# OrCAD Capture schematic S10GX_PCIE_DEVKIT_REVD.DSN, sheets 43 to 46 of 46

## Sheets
43 Power - 5V, 2.5V, 2.4V, 1V: size C
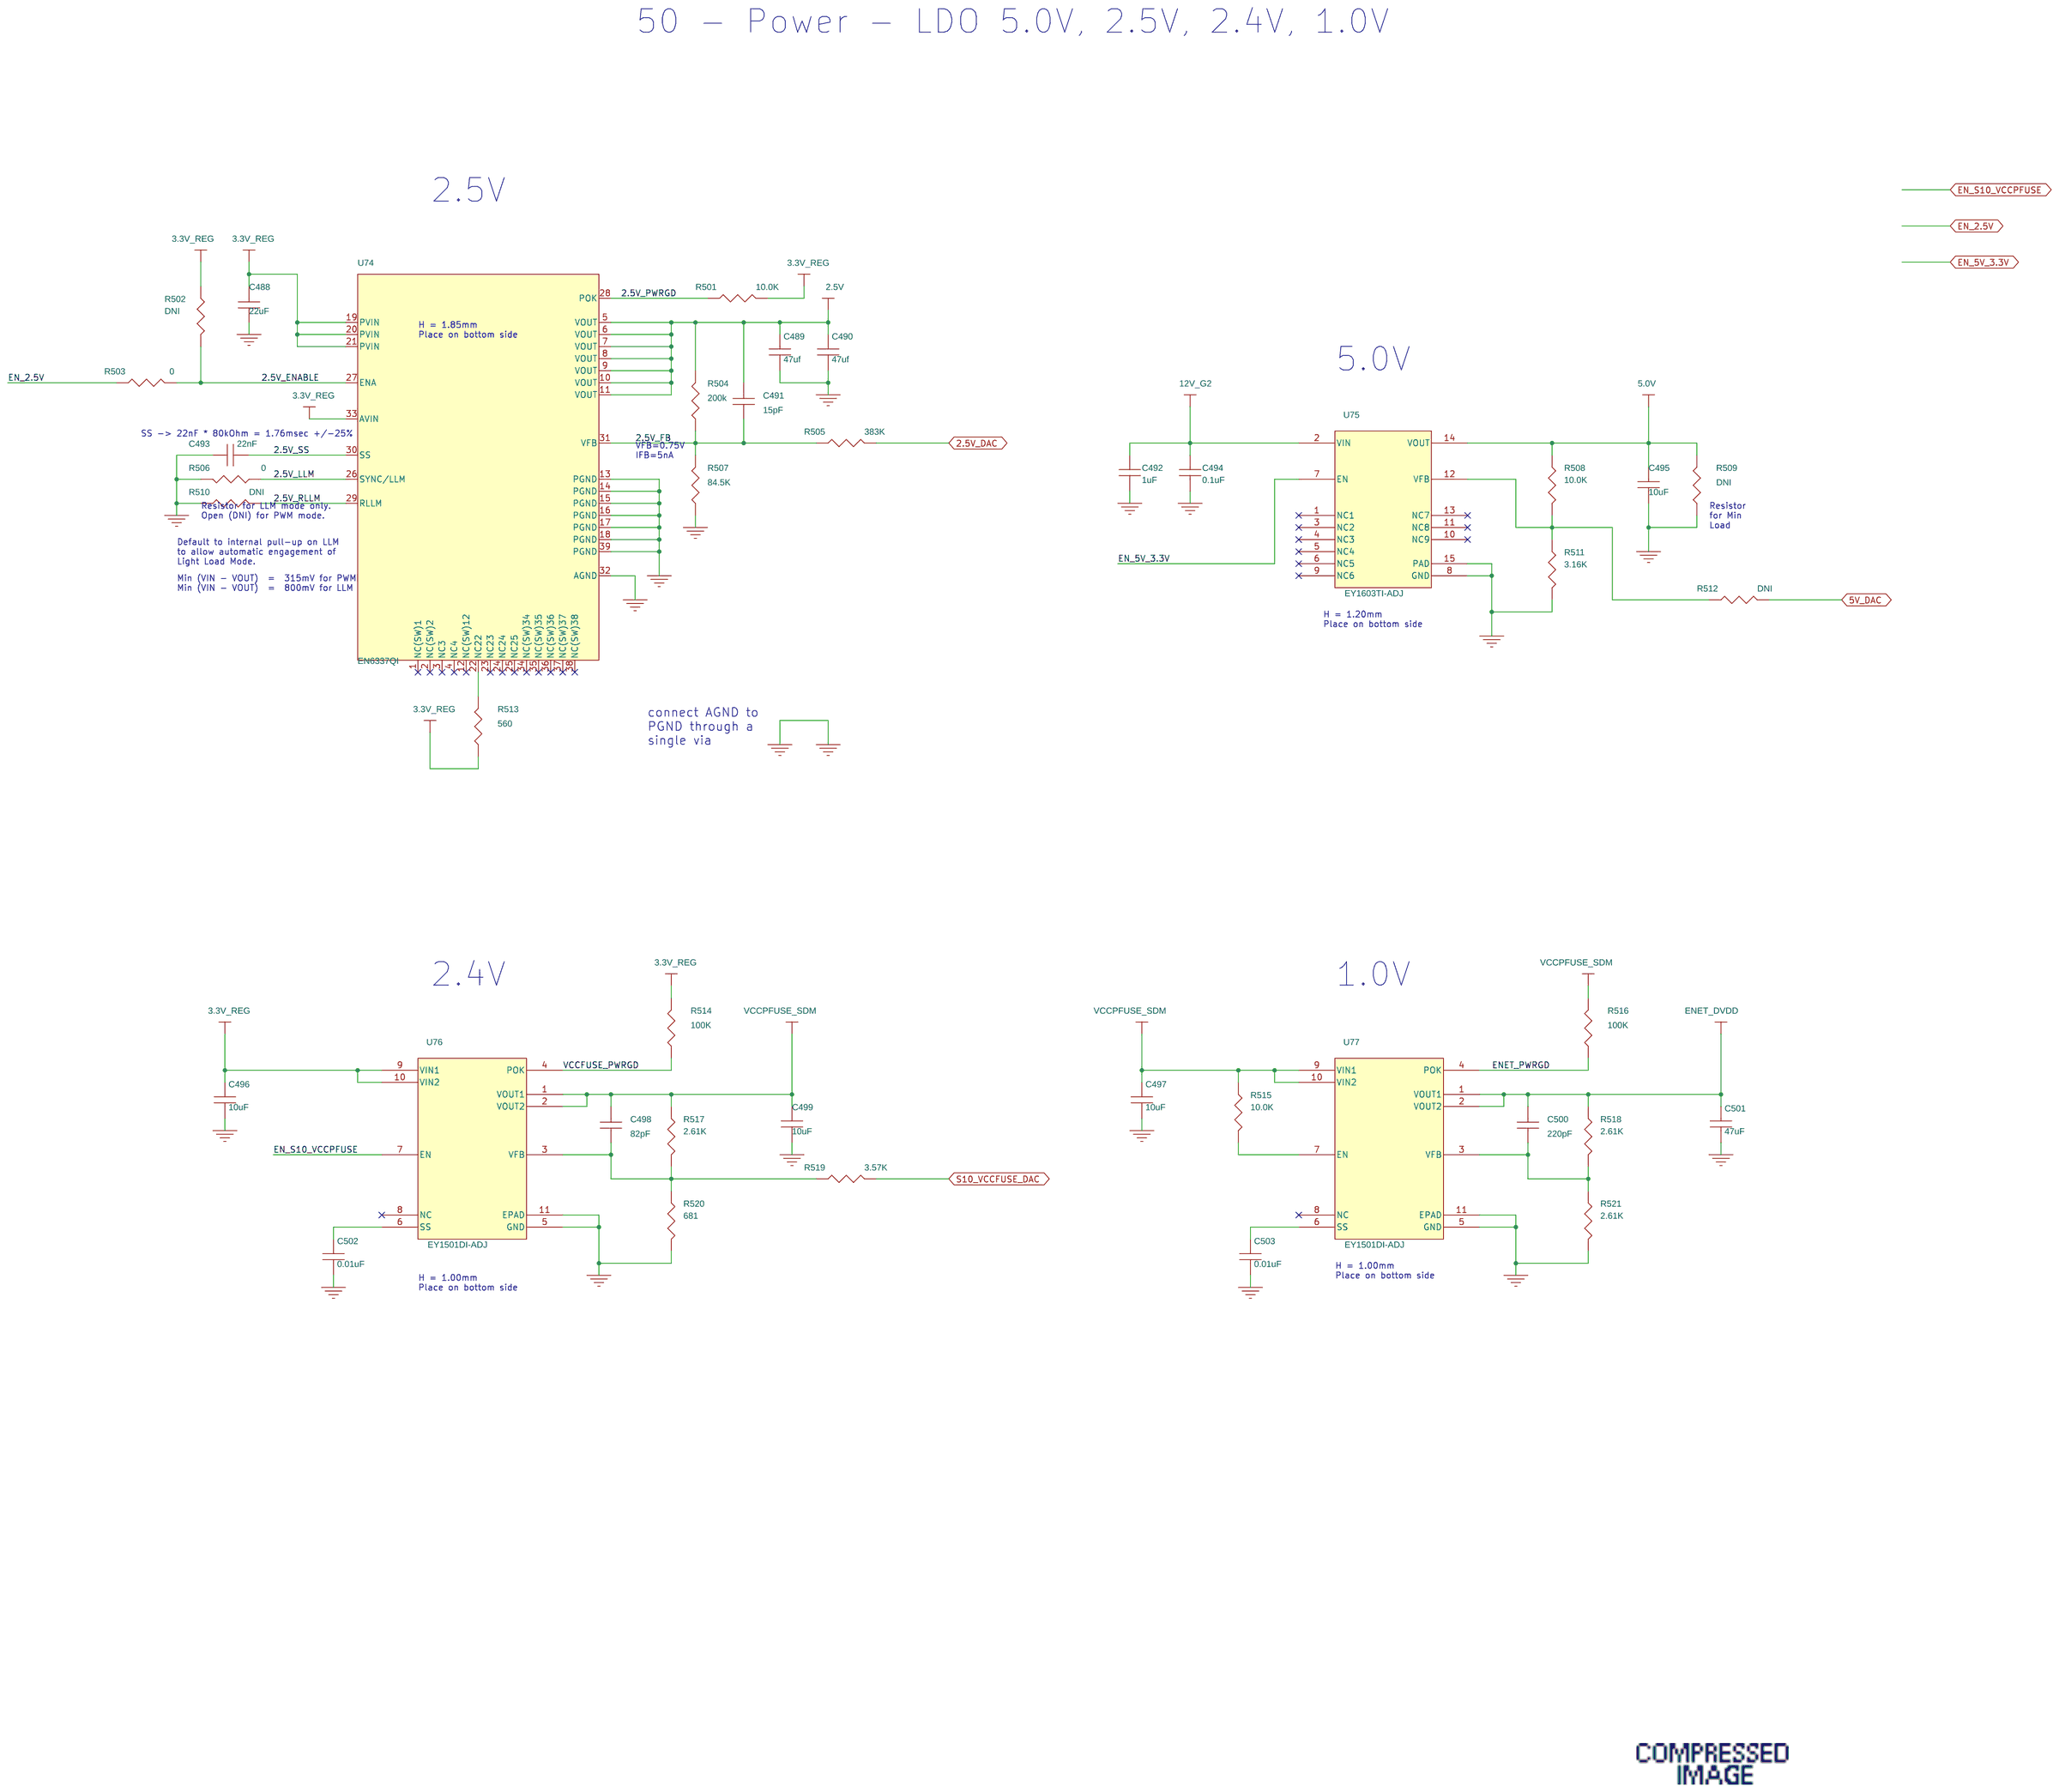
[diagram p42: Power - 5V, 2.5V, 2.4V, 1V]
44 Power - VCCIO3V: size C
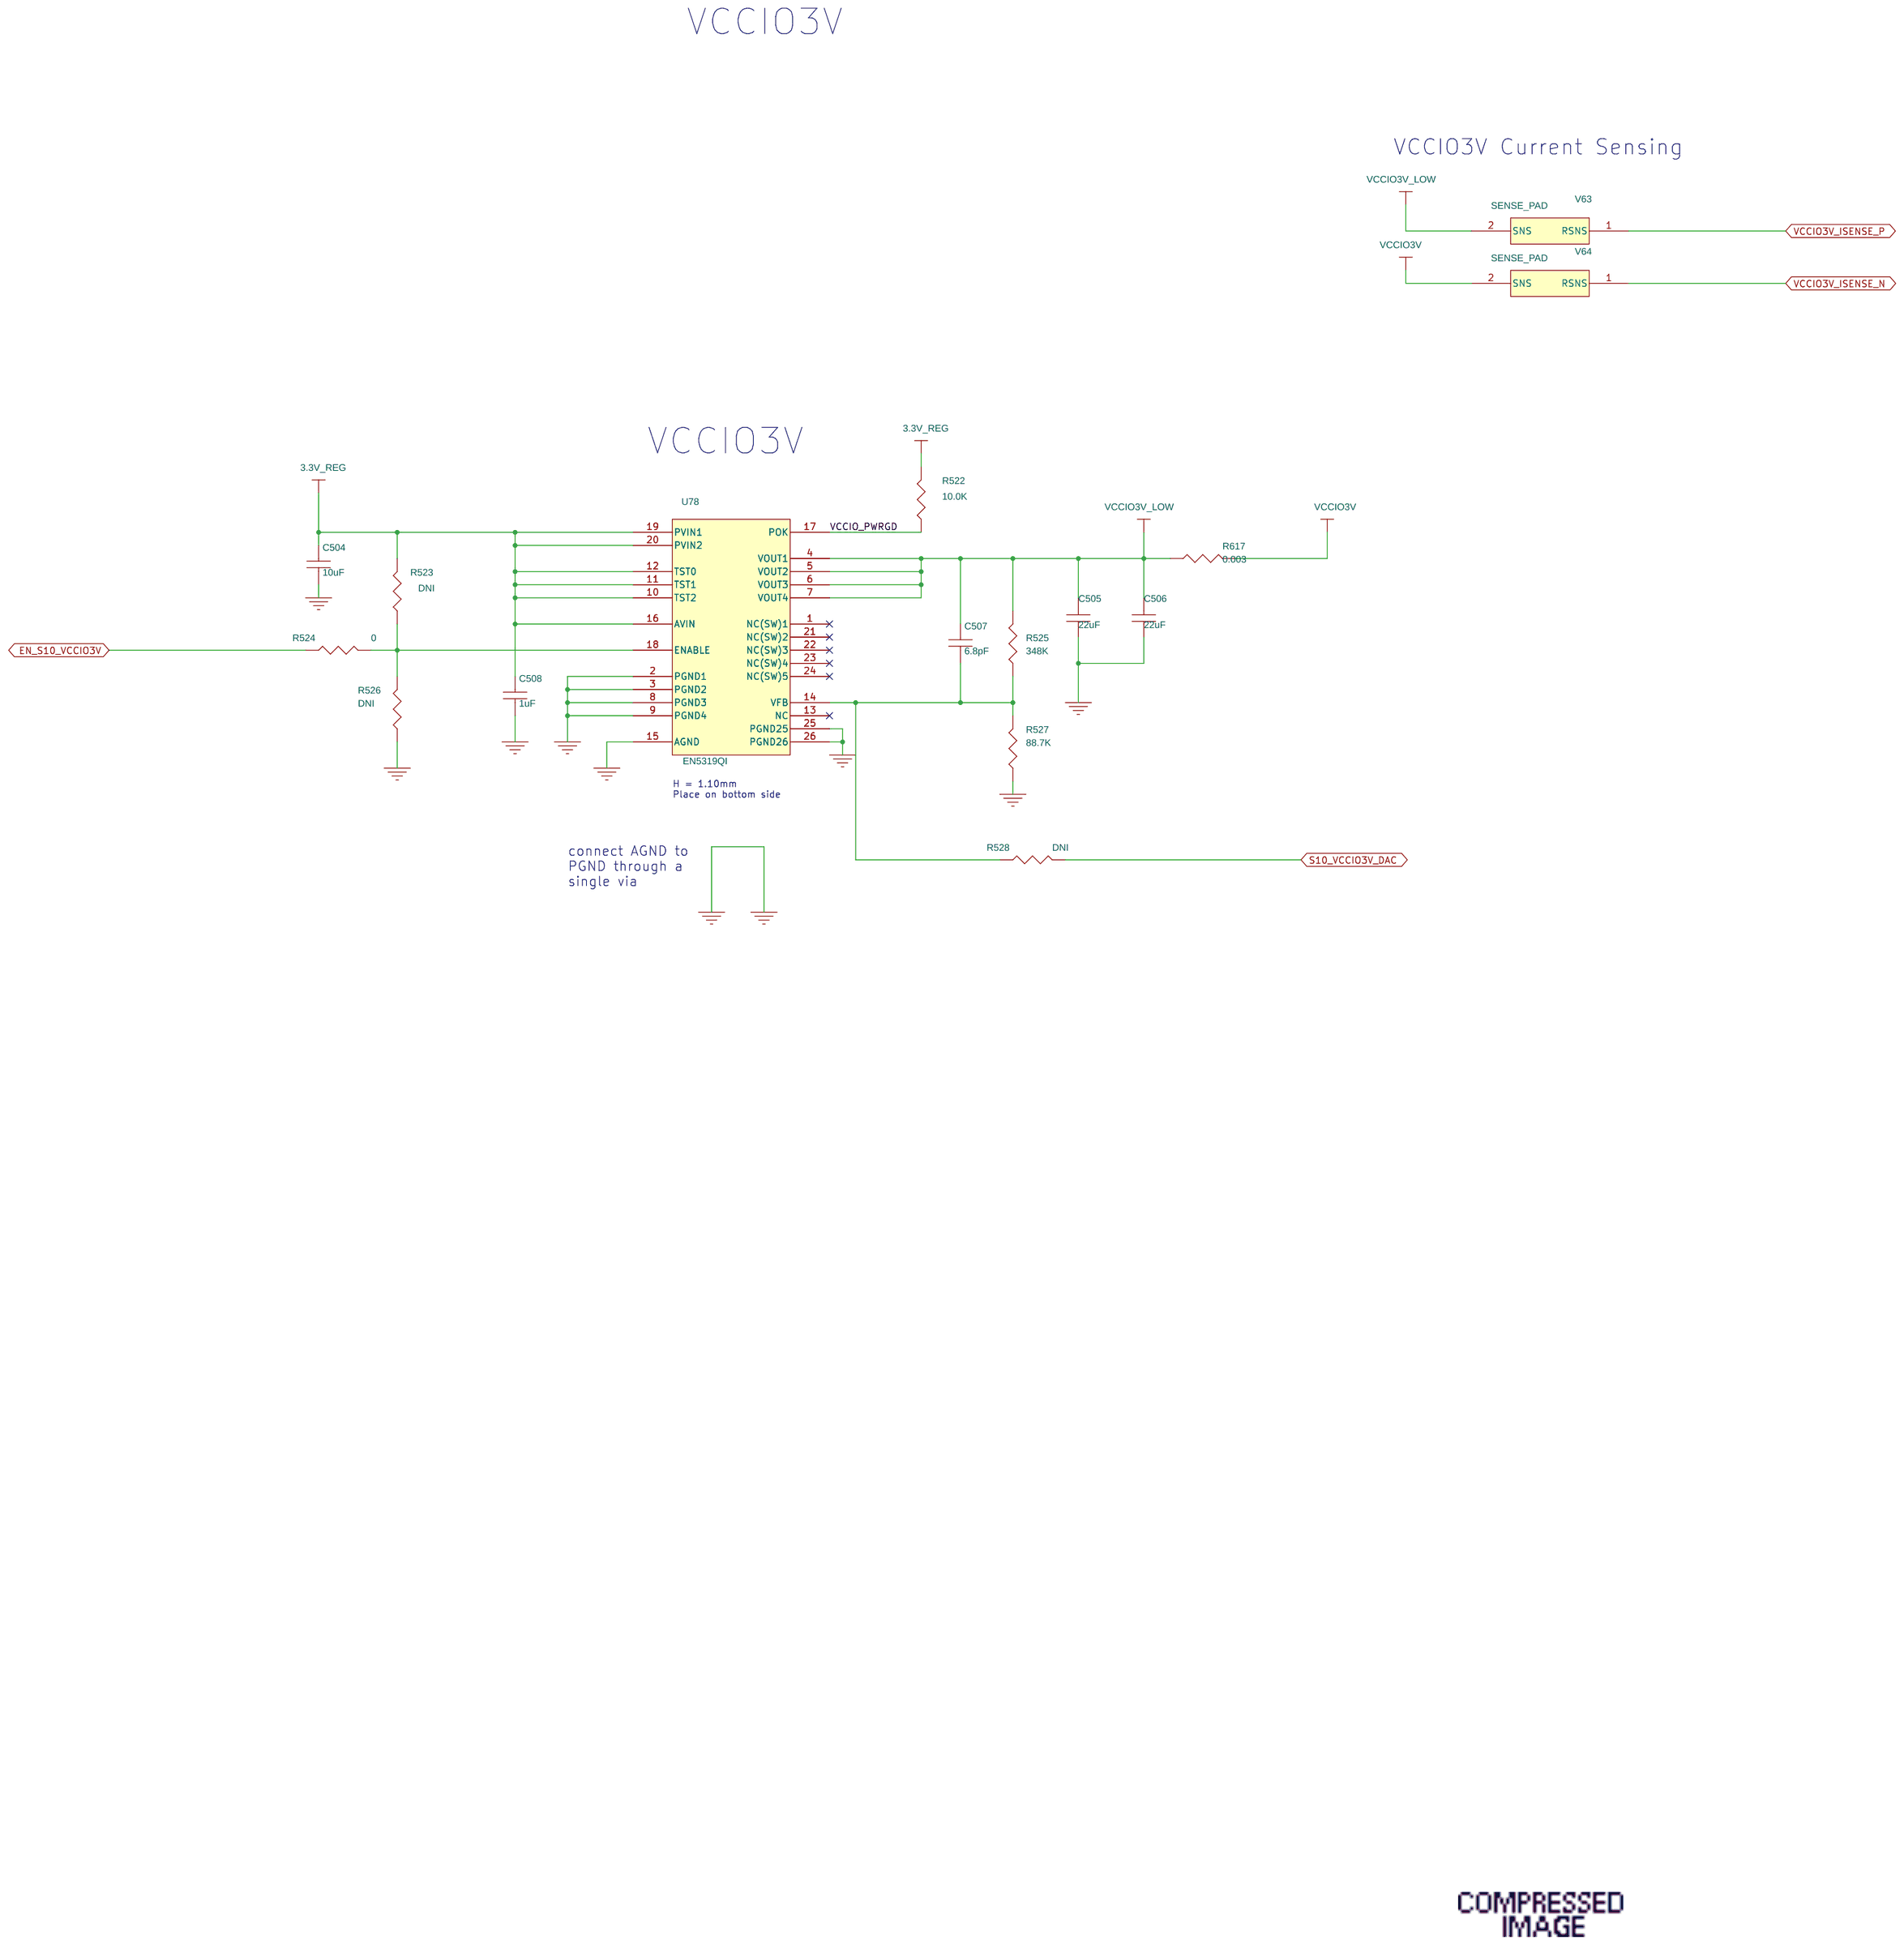
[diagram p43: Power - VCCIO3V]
45 S10 Decoupling: size C
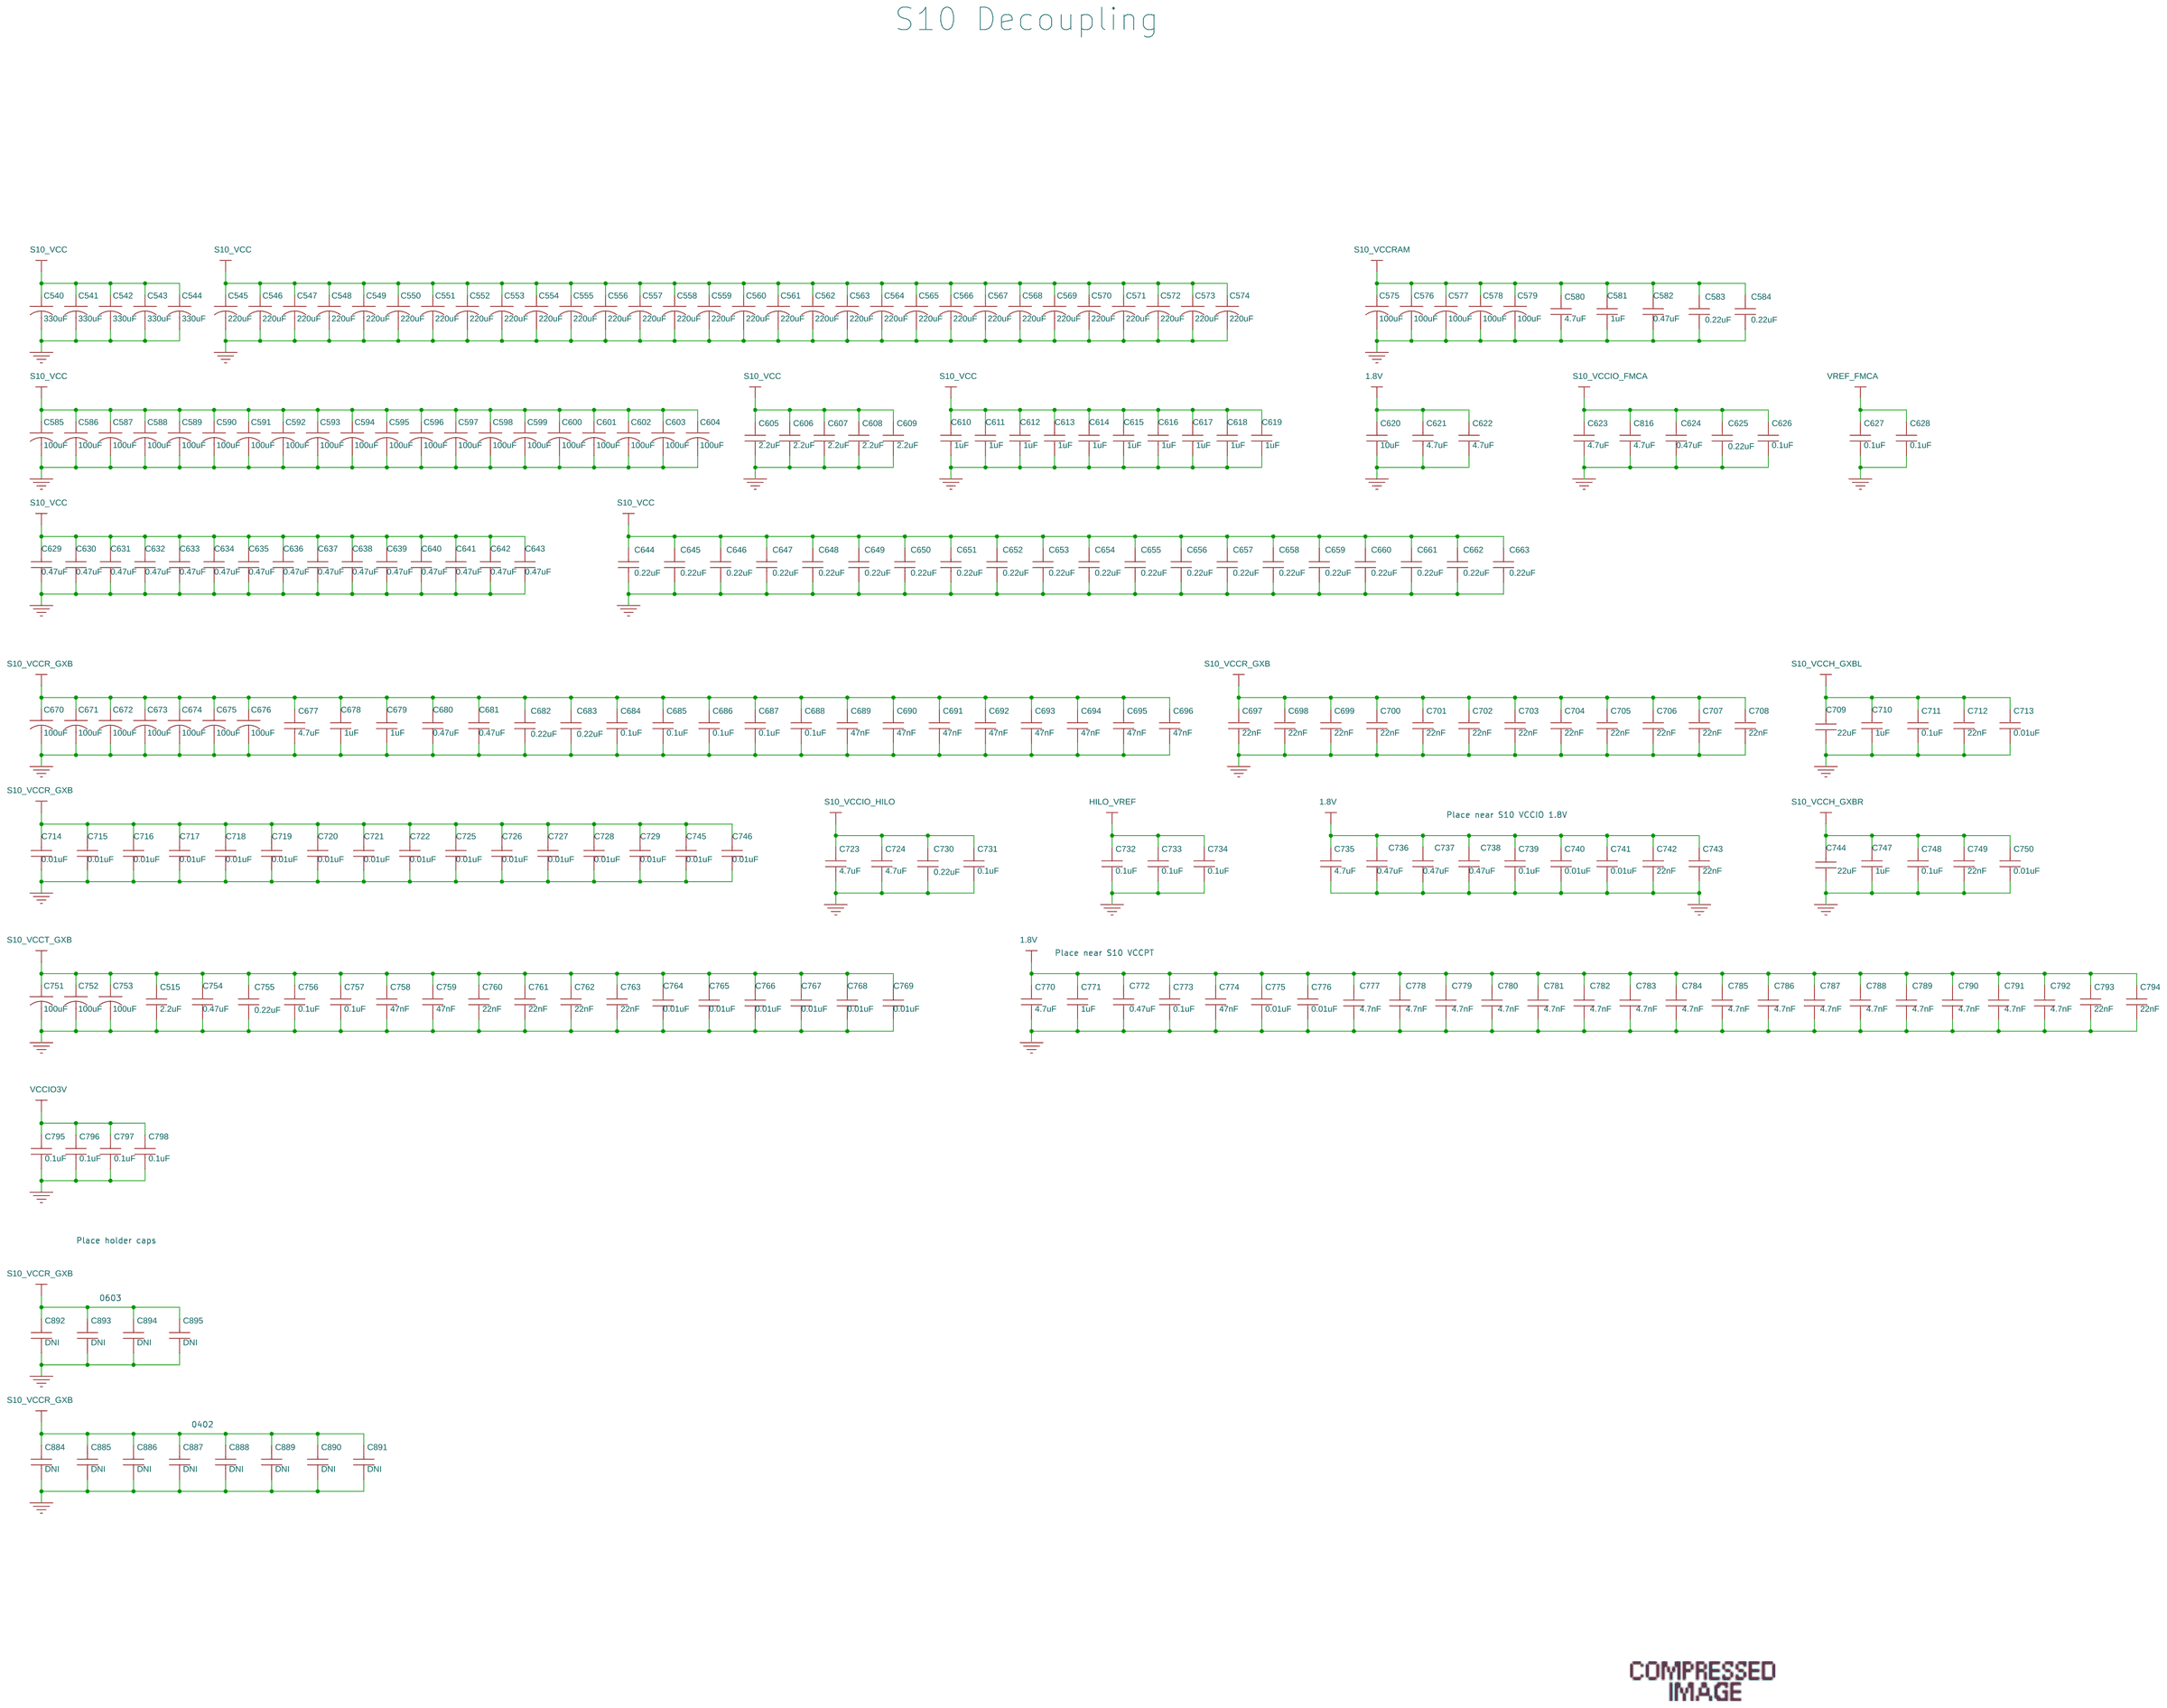
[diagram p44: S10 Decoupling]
46 Fast Power-Down Discharge: size C
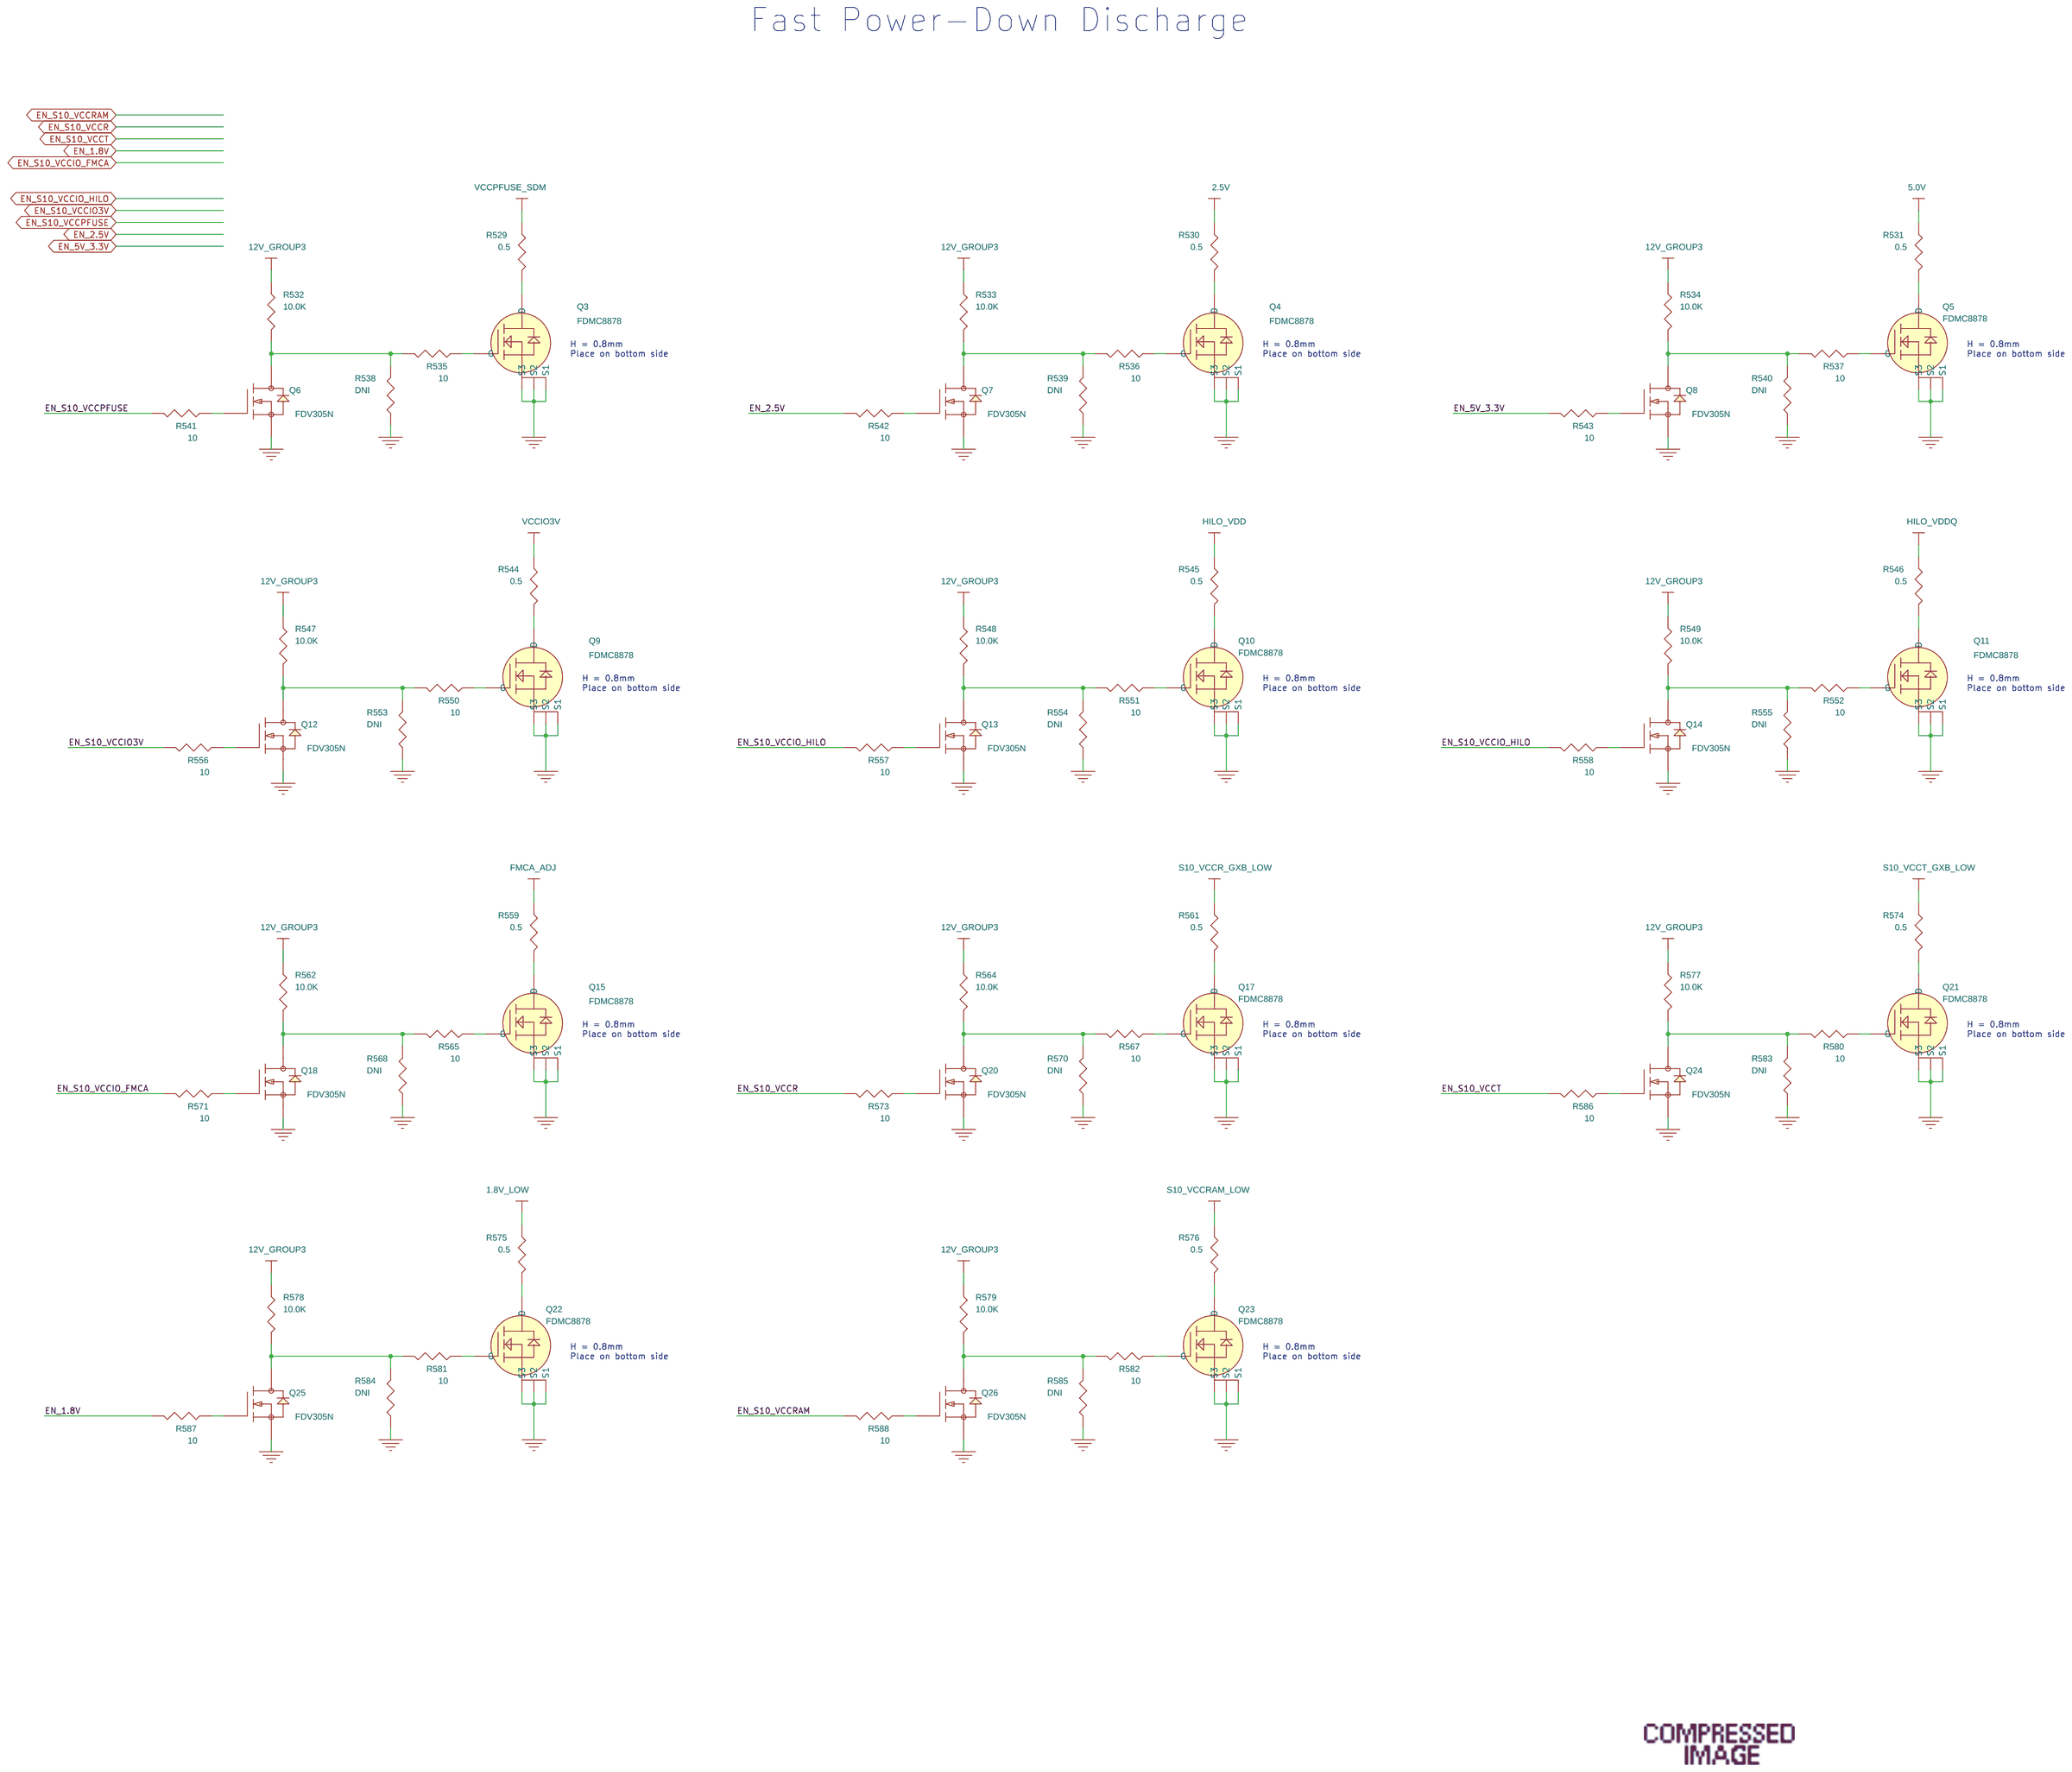
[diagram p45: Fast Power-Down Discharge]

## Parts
sheet Fast Power-Down Discharge
Q3  FDMC8878  [FDMC8878_VER2]
Q4  FDMC8878  [FDMC8878_VER2]
Q5  FDMC8878  [FDMC8878_VER2]
Q6  FDV305N  [SOT23]
Q7  FDV305N  [SOT23]
Q8  FDV305N  [SOT23]
Q9  FDMC8878  [FDMC8878_VER2]
Q10  FDMC8878  [FDMC8878_VER2]
Q11  FDMC8878  [FDMC8878_VER2]
Q12  FDV305N  [SOT23]
Q13  FDV305N  [SOT23]
Q14  FDV305N  [SOT23]
Q15  FDMC8878  [FDMC8878_VER2]
Q17  FDMC8878  [FDMC8878_VER2]
Q18  FDV305N  [SOT23]
Q20  FDV305N  [SOT23]
Q21  FDMC8878  [FDMC8878_VER2]
Q22  FDMC8878  [FDMC8878_VER2]
Q23  FDMC8878  [FDMC8878_VER2]
Q24  FDV305N  [SOT23]
Q25  FDV305N  [SOT23]
Q26  FDV305N  [SOT23]
R529  0.5  [2512]
R530  0.5  [2512]
R531  0.5  [2512]
R532  10.0K  [0402]
R533  10.0K  [0402]
R534  10.0K  [0402]
R535  10  [0402]
R536  10  [0402]
R537  10  [0402]
R538  DNI  [0402]
R539  DNI  [0402]
R540  DNI  [0402]
R541  10  [0402]
R542  10  [0402]
R543  10  [0402]
R544  0.5  [2512]
R545  0.5  [2512]
R546  0.5  [2512]
R547  10.0K  [0402]
R548  10.0K  [0402]
R549  10.0K  [0402]
R550  10  [0402]
R551  10  [0402]
R552  10  [0402]
R553  DNI  [0402]
R554  DNI  [0402]
R555  DNI  [0402]
R556  10  [0402]
R557  10  [0402]
R558  10  [0402]
R559  0.5  [2512]
R561  0.5  [2512]
R562  10.0K  [0402]
R564  10.0K  [0402]
R565  10  [0402]
R567  10  [0402]
R568  DNI  [0402]
R570  DNI  [0402]
R571  10  [0402]
R573  10  [0402]
R574  0.5  [2512]
R575  0.5  [2512]
R576  0.5  [2512]
R577  10.0K  [0402]
R578  10.0K  [0402]
R579  10.0K  [0402]
R580  10  [0402]
R581  10  [0402]
R582  10  [0402]
R583  DNI  [0402]
R584  DNI  [0402]
R585  DNI  [0402]
R586  10  [0402]
R587  10  [0402]
R588  10  [0402]
sheet Power - 5V, 2.5V, 2.4V, 1V
C488  22uF  [1206]
C489  47uf  [1206]
C490  47uf  [1206]
C491  15pF  [0402]
C492  1uF  [0603]
C493  22nF  [0402]
C494  0.1uF  [0402]
C495  10uF  [0603]
C496  10uF  [0603]
C497  10uF  [0603]
C498  82pF  [0402]
C499  10uF  [0603]
C500  220pF  [0402]
C501  47uF  [1206]
C502  0.01uF  [0402]
C503  0.01uF  [0402]
R501  10.0K  [0402]
R502  DNI  [0402]
R503  0  [0402]
R504  200k  [0402]
R505  383K  [0402]
R506  0  [0402]
R507  84.5K  [0402]
R508  10.0K  [0402]
R509  DNI  [0402]
R510  DNI  [0402]
R511  3.16K  [0402]
R512  DNI  [0402]
R513  560  [0402]
R514  100K  [0402]
R515  10.0K  [0402]
R516  100K  [0402]
R517  2.61K  [0402]
R518  2.61K  [0402]
R519  3.57K  [0402]
R520  681  [0402]
R521  2.61K  [0402]
U74  EN6337QI  [QFN38-ENPIRON]
U75  EY1603TI-ADJ  [HTSSOP-14]
U76  EY1501DI-ADJ  [DFN-10]
U77  EY1501DI-ADJ  [DFN-10]
sheet Power - VCCIO3V
C504  10uF  [0603]
C505  22uF  [1206]
C506  22uF  [1206]
C507  6.8pF  [0402]
C508  1uF  [0402]
R522  10.0K  [0402]
R523  DNI  [0402]
R524  0  [0402]
R525  348K  [0402]
R526  DNI  [0402]
R527  88.7K  [0402]
R528  DNI  [0402]
R617  0.003  [WSL2010]
U78  EN5319QI  [EN5319QI]
V63  SENSE_PAD  [SENSE]
V64  SENSE_PAD  [SENSE]
sheet S10 Decoupling
C515  2.2uF  [0603]
C540  330uF  [7343-V_LOW-PROFILE]
C541  330uF  [7343-V_LOW-PROFILE]
C542  330uF  [7343-V_LOW-PROFILE]
C543  330uF  [7343-V_LOW-PROFILE]
C544  330uF  [7343-V_LOW-PROFILE]
C545  220uF  [1206]
C546  220uF  [1206]
C547  220uF  [1206]
C548  220uF  [1206]
C549  220uF  [1206]
C550  220uF  [1206]
C551  220uF  [1206]
C552  220uF  [1206]
C553  220uF  [1206]
C554  220uF  [1206]
C555  220uF  [1206]
C556  220uF  [1206]
C557  220uF  [1206]
C558  220uF  [1206]
C559  220uF  [1206]
C560  220uF  [1206]
C561  220uF  [1206]
C562  220uF  [1206]
C563  220uF  [1206]
C564  220uF  [1206]
C565  220uF  [1206]
C566  220uF  [1206]
C567  220uF  [1206]
C568  220uF  [1206]
C569  220uF  [1206]
C570  220uF  [1206]
C571  220uF  [1206]
C572  220uF  [1206]
C573  220uF  [1206]
C574  220uF  [1206]
C575  100uF  [Avx-1210_case-b]
C576  100uF  [Avx-1210_case-b]
C577  100uF  [Avx-1210_case-b]
C578  100uF  [Avx-1210_case-b]
C579  100uF  [Avx-1210_case-b]
C580  4.7uF  [0402]
C581  1uF  [0402]
C582  0.47uF  [0402]
C583  0.22uF  [0402]
C584  0.22uF  [0402]
C585  100uF  [Avx-1210_case-b]
C586  100uF  [Avx-1210_case-b]
C587  100uF  [Avx-1210_case-b]
C588  100uF  [Avx-1210_case-b]
C589  100uF  [Avx-1210_case-b]
C590  100uF  [Avx-1210_case-b]
C591  100uF  [Avx-1210_case-b]
C592  100uF  [Avx-1210_case-b]
C593  100uF  [Avx-1210_case-b]
C594  100uF  [Avx-1210_case-b]
C595  100uF  [Avx-1210_case-b]
C596  100uF  [Avx-1210_case-b]
C597  100uF  [Avx-1210_case-b]
C598  100uF  [Avx-1210_case-b]
C599  100uF  [Avx-1210_case-b]
C600  100uF  [Avx-1210_case-b]
C601  100uF  [Avx-1210_case-b]
C602  100uF  [Avx-1210_case-b]
C603  100uF  [Avx-1210_case-b]
C604  100uF  [Avx-1210_case-b]
C605  2.2uF  [0603]
C606  2.2uF  [0603]
C607  2.2uF  [0603]
C608  2.2uF  [0603]
C609  2.2uF  [0603]
C610  1uF  [0402]
C611  1uF  [0402]
C612  1uF  [0402]
C613  1uF  [0402]
C614  1uF  [0402]
C615  1uF  [0402]
C616  1uF  [0402]
C617  1uF  [0402]
C618  1uF  [0402]
C619  1uF  [0402]
C620  10uF  [0603]
C621  4.7uF  [0402]
C622  4.7uF  [0402]
C623  4.7uF  [0402]
C624  0.47uF  [0402]
C625  0.22uF  [0402]
C626  0.1uF  [0402]
C627  0.1uF  [0402]
C628  0.1uF  [0402]
C629  0.47uF  [0402]
C630  0.47uF  [0402]
C631  0.47uF  [0402]
C632  0.47uF  [0402]
C633  0.47uF  [0402]
C634  0.47uF  [0402]
C635  0.47uF  [0402]
C636  0.47uF  [0402]
C637  0.47uF  [0402]
C638  0.47uF  [0402]
C639  0.47uF  [0402]
C640  0.47uF  [0402]
C641  0.47uF  [0402]
C642  0.47uF  [0402]
C643  0.47uF  [0402]
C644  0.22uF  [0402]
C645  0.22uF  [0402]
C646  0.22uF  [0402]
C647  0.22uF  [0402]
C648  0.22uF  [0402]
C649  0.22uF  [0402]
C650  0.22uF  [0402]
C651  0.22uF  [0402]
C652  0.22uF  [0402]
C653  0.22uF  [0402]
C654  0.22uF  [0402]
C655  0.22uF  [0402]
C656  0.22uF  [0402]
C657  0.22uF  [0402]
C658  0.22uF  [0402]
C659  0.22uF  [0402]
C660  0.22uF  [0402]
C661  0.22uF  [0402]
C662  0.22uF  [0402]
C663  0.22uF  [0402]
C670  100uF  [Avx-1210_case-b]
C671  100uF  [Avx-1210_case-b]
C672  100uF  [Avx-1210_case-b]
C673  100uF  [Avx-1210_case-b]
C674  100uF  [Avx-1210_case-b]
C675  100uF  [Avx-1210_case-b]
C676  100uF  [Avx-1210_case-b]
C677  4.7uF  [0402]
C678  1uF  [0402]
C679  1uF  [0402]
C680  0.47uF  [0402]
C681  0.47uF  [0402]
C682  0.22uF  [0402]
C683  0.22uF  [0402]
C684  0.1uF  [0402]
C685  0.1uF  [0402]
C686  0.1uF  [0402]
C687  0.1uF  [0402]
C688  0.1uF  [0402]
C689  47nF  [0402]
C690  47nF  [0402]
C691  47nF  [0402]
C692  47nF  [0402]
C693  47nF  [0402]
C694  47nF  [0402]
C695  47nF  [0402]
C696  47nF  [0402]
C697  22nF  [0402]
C698  22nF  [0402]
C699  22nF  [0402]
C700  22nF  [0402]
C701  22nF  [0402]
C702  22nF  [0402]
C703  22nF  [0402]
C704  22nF  [0402]
C705  22nF  [0402]
C706  22nF  [0402]
C707  22nF  [0402]
C708  22nF  [0402]
C709  22uF  [1206]
C710  1uF  [0402]
C711  0.1uF  [0402]
C712  22nF  [0402]
C713  0.01uF  [0402]
C714  0.01uF  [0402]
C715  0.01uF  [0402]
C716  0.01uF  [0402]
C717  0.01uF  [0402]
C718  0.01uF  [0402]
C719  0.01uF  [0402]
C720  0.01uF  [0402]
C721  0.01uF  [0402]
C722  0.01uF  [0402]
C723  4.7uF  [0402]
C724  4.7uF  [0402]
C725  0.01uF  [0402]
C726  0.01uF  [0402]
C727  0.01uF  [0402]
C728  0.01uF  [0402]
C729  0.01uF  [0402]
C730  0.22uF  [0402]
C731  0.1uF  [0402]
C732  0.1uF  [0402]
C733  0.1uF  [0402]
C734  0.1uF  [0402]
C735  4.7uF  [0402]
C736  0.47uF  [0402]
C737  0.47uF  [0402]
C738  0.47uF  [0402]
C739  0.1uF  [0402]
C740  0.01uF  [0402]
C741  0.01uF  [0402]
C742  22nF  [0402]
C743  22nF  [0402]
C744  22uF  [1206]
C745  0.01uF  [0402]
C746  0.01uF  [0402]
C747  1uF  [0402]
C748  0.1uF  [0402]
C749  22nF  [0402]
C750  0.01uF  [0402]
C751  100uF  [Avx-1210_case-b]
C752  100uF  [Avx-1210_case-b]
C753  100uF  [Avx-1210_case-b]
C754  0.47uF  [0402]
C755  0.22uF  [0402]
C756  0.1uF  [0402]
C757  0.1uF  [0402]
C758  47nF  [0402]
C759  47nF  [0402]
C760  22nF  [0402]
C761  22nF  [0402]
C762  22nF  [0402]
C763  22nF  [0402]
C764  0.01uF  [0402]
C765  0.01uF  [0402]
C766  0.01uF  [0402]
C767  0.01uF  [0402]
C768  0.01uF  [0402]
C769  0.01uF  [0402]
C770  4.7uF  [0402]
C771  1uF  [0402]
C772  0.47uF  [0402]
C773  0.1uF  [0402]
C774  47nF  [0402]
C775  0.01uF  [0402]
C776  0.01uF  [0402]
C777  4.7nF  [0402]
C778  4.7nF  [0402]
C779  4.7nF  [0402]
C780  4.7nF  [0402]
C781  4.7nF  [0402]
C782  4.7nF  [0402]
C783  4.7nF  [0402]
C784  4.7nF  [0402]
C785  4.7nF  [0402]
C786  4.7nF  [0402]
C787  4.7nF  [0402]
C788  4.7nF  [0402]
C789  4.7nF  [0402]
C790  4.7nF  [0402]
C791  4.7nF  [0402]
C792  4.7nF  [0402]
C793  22nF  [0402]
C794  22nF  [0402]
C795  0.1uF  [0402]
C796  0.1uF  [0402]
C797  0.1uF  [0402]
C798  0.1uF  [0402]
C816  4.7uF  [0402]
C884  DNI  [0402]
C885  DNI  [0402]
C886  DNI  [0402]
C887  DNI  [0402]
C888  DNI  [0402]
C889  DNI  [0402]
C890  DNI  [0402]
C891  DNI  [0402]
C892  DNI  [0603]
C893  DNI  [0603]
C894  DNI  [0603]
C895  DNI  [0603]

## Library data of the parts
Q3-Q5 Q9-Q11 Q15 Q17 Q21-Q23 = FDMC8878_VER2: MOSFET - N-CHANNEL Pwr Trench 16.5A 30V 14MOHM Power33; Item Num: P18-31175R; Manufacturer: Fairchild Semiconductor
Q6-Q8 Q12-Q14 Q18 Q20 Q24-Q26 = PWRMOSFET_EN_GSD_0: IC, MOSFET, N-Channel, 20V; Item Num: P18-31002R; Manufacturer: Fairchild; Manufacturer Part Num: FDV305N_NL
R529-R531 R544-R546 R559 R561 R574-R576 = RESISTOR: SMD 1Watt 0.5Ohms 1% 2512; Item Num: P02-17641R; Lead Free Status: No; Manufacturer: Vishay; Manufacturer Part Num: WSLT2512R5000FEA; Num Pins: 2; Part Class: Resistors
R508 R515 R532-R534 R547-R549 R562 R564 R577-R579 = RESISTOR: RES,10.0K OHMS,1.0%,1/16W, 0402; AGILE_LINK: http://sj-agile9app/Agile/PLMServlet?action=OpenEmailObject&classid=10000&objid=146548997; Item Num: P02-11364R; LIFECYCLE_PHASE: Active; Lead Free Status: No; MFR_LIFECYCLE: Active; Manufacturer: Panasonic; Manufacturer Part Num: ERJ-2RKF1002X; Num Pins: 2; PART_SUBCLASS: RESISTORS; POWER: 1/16W; RESISTANCE: 10K; RoHS Compliant: Yes; TOLERANCE: +/-1%
R535-R537 R541-R543 R550-R552 R556-R558 R565 R567 R571 R573 R580-R582 R586-R588 = RESISTOR: RES, 10 OHM, 1%, 1/16W, 0402; AGILE_LINK: http://sj-agile9app/Agile/PLMServlet?action=OpenEmailObject&classid=10000&objid=146932246; Item Num: P02-16268R; LIFECYCLE_PHASE: Active; MFR_LIFECYCLE: Active; Manufacturer: Panasonic; Manufacturer Part Num: ERJ-2RKF10R0X; Num Pins: 2; PART_SUBCLASS: RESISTORS; POWER: 1/16W; RoHS Compliant: RoHS Compliant; TOLERANCE: +/-1%
R538-R540 R553-R555 R568 R570 R583-R585 = RESISTOR: RES,4.70K OHMS,1.0%,1/16W,0402; AGILE_LINK: http://sj-agile9app/Agile/PLMServlet?action=OpenEmailObject&classid=10000&objid=146753272; Item Num: P02-11384R; LIFECYCLE_PHASE: Active; Lead Free Status: No; MFR_LIFECYCLE: Active; Manufacturer: Vishay; Manufacturer Part Num: CRCW04024K70FKED; Num Pins: 2; PART_SUBCLASS: RESISTORS; POWER: 1/16W; RESISTANCE: 4.7K; RoHS Compliant: Yes; TOLERANCE: +/-1%
C488 C505 C506 C709 C744 = CAP: CAP - CER, 22UF, 25V, 10%, X5R, 1206; Item Num: P03-17640R; Lead Free Status: Yes; Manufacturer: Murata; Manufacturer Part Num: GRM31CR61E226KE15L; Num Pins: 2; Part Class: Capacitors; Price: 0; RoHS Compliant: Yes
C489 C490 = CAP: CAP -   CER, 47UF, 10V, 20%, X5R, 1206, SMD; AGILE_LINK: http://sj-agile9app/Agile/PLMServlet?action=OpenEmailObject&classid=10000&objid=146494148; CAPACITANCE: 47uF; Item Num: P03-17650R; LIFECYCLE_PHASE: Active; MFR_LIFECYCLE: Active; Manufacturer: Taiyo Yuden; Manufacturer Part Num: LMK316BJ476ML-T; Num Pins: 2; PART_SUBCLASS: CAPACITORS; RATED_VOLTAGE: 10V; RoHS Compliant: RoHS Compliant; TOLERANCE: +/-20%
C491 = CAP: CAP - CER ,15PF, 50V, 5%, C0G, 0402; Item Num: P03-15372R; Lead Free Status: Yes; Manufacturer: Murata; Manufacturer Part Num: GRM1555C1H150JZ01D; Num Pins: 2; Part Class: Capacitors; Price: 0; RoHS Compliant: Yes
C492 = CAP: CAP - CER, 1UF, 25V, +/-10%, X5R, 0603 SMD; AGILE_LINK: http://sj-agile9app/Agile/PLMServlet?action=OpenEmailObject&classid=10000&objid=213459527; Item Num: P03-16324R; LIFECYCLE_PHASE: Active; Lead Free Status: Lead Free; MFR_LIFECYCLE: Active; Manufacturer: Murata; Manufacturer Part Num: GRM188R61E105KA12D; Num Pins: 2; PART_SUBCLASS: CAPACITORS; Part Class: CAPACITORS; RATED_VOLTAGE: 25V; RoHS Compliant: RoHS Compliant; TOLERANCE: +/-10%
C493 C697-C708 C712 C742 C743 C749 C760-C763 C793 C794 = CAP: CAP - CER, 22NF, 25V, +/-10%, X7R, 0402 SMD; AGILE_LINK: http://sj-agile9app/Agile/PLMServlet?action=OpenEmailObject&classid=10000&objid=256989767; CAPACITANCE: 22000pF; Item Num: P03-16317R; LIFECYCLE_PHASE: Active; Lead Free Status: Lead Free; MFR_LIFECYCLE: Active; Manufacturer: Murata; Manufacturer Part Num: GRM155R71E223KA61D; Num Pins: 2; PART_SUBCLASS: CAPACITORS; RATED_VOLTAGE: 25V; RoHS Compliant: RoHS Compliant; TOLERANCE: +80%/-20%
C494 = CAP: CAP - CERAMIC,  0.1UF 0402 25VDC Y5V; AGILE_LINK: http://sj-agile9app/Agile/PLMServlet?action=OpenEmailObject&classid=10000&objid=213459527; Item Num: P03-15057R; LIFECYCLE_PHASE: Active; Lead Free Status: Lead Free; MFR_LIFECYCLE: Active; Manufacturer: Murata; Manufacturer Part Num: GRM155F51E104ZA01D; Num Pins: 2; PART_SUBCLASS: CAPACITORS; Part Class: CAPACITORS; RATED_VOLTAGE: 25V; RoHS Compliant: RoHS Compliant; TOLERANCE: +80%/-20%
C495 C499 = CAP: CAP CER 10UF 25V 20% JB 0603; Item Num: P03-17784R; Lead Free Status: Yes; Manufacturer: TDK; Manufacturer Part Num: C1608JB1E106M080AC; Num Pins: 2; Part Class: Capacitors; Price: 0; RoHS Compliant: Yes
C496 C497 C504 C620 = CAP: CAP - CER 10UF 6.3V 20% X5R 0603; Item Num: P03-15733R; Lead Free Status: Lead Free; Manufacturer: Murata; Manufacturer Part Num: GRM188R60J106ME47X; Num Pins: 2; PART_SUBCLASS: CAPACITORS; Part Class: CAPACITORS; RoHS Compliant: RoHS Compliant
C498 = CAP: CAP - CER, 82PF, 5%, 50V, C0G, 0402; Dielectric: X5R; Item Num: P03-17372R; Lead Free Status: Yes; Manufacturer: Yageo; Manufacturer Part Num: CC0402JRNPO9BN820; Num Pins: 2; Part Class: CAPACITORS; RoHS Compliant: Yes; Tolerance: 5%
C500 = CAP: CAP - CERAMIC, 220PF, 10%, 50V, 0402, X7R; Dielectric: X5R; Item Num: P03-15090R; Lead Free Status: Yes; Manufacturer: Murata; Manufacturer Part Num: GRM155R71H221KA01D; Manufacturer's Part No.: GRM155R71H221KA01D; Num Pins: 2; Part Class: CAPACITORS; Price: 0.07; RoHS Compliant: Yes; Tolerance: 10%
C501 = CAP: CAP -   CER, 47UF, 10V, 20%, X5R, 1206, SMD; AGILE_LINK: http://sj-agile9app/Agile/PLMServlet?action=OpenEmailObject&classid=10000&objid=146494148; Item Num: P03-17650R; LIFECYCLE_PHASE: Active; MFR_LIFECYCLE: Active; Manufacturer: Taiyo Yuden; Manufacturer Part Num: LMK316BJ476ML-T; Num Pins: 2; PART_SUBCLASS: CAPACITORS; RATED_VOLTAGE: 10V; RoHS Compliant: RoHS Compliant; TOLERANCE: +/-20%
C502 C503 C713-C722 C725-C729 C740 C741 C745 C746 C750 C764-C769 C775 C776 = CAP: CAP - CER, 10NF, 50V, +/-10%, X7R, 0402 SMD; Dielectric: X5R; Item Num: P03-16318R; Lead Free Status: Yes; Manufacturer: Murata; Manufacturer Part Num: GRM155R71H103KA88D; Manufacturer's Part No.: GRM155R71H103KA88D; Num Pins: 2; Part Class: CAPACITORS; Price: 0.07; RoHS Compliant: Yes; Tolerance: 10%
R501 R522 = RESISTOR: RES,10.0K OHMS,1.0%,1/16W, 0402; AGILE_LINK: http://sj-agile9app/Agile/PLMServlet?action=OpenEmailObject&classid=10000&objid=146548997; Item Num: P02-11364R; LIFECYCLE_PHASE: Active; Lead Free Status: No; MFR_LIFECYCLE: Active; Manufacturer: Panasonic; Manufacturer Part Num: ERJ-2RKF1002X; Num Pins: 2; PART_SUBCLASS: RESISTORS; POWER: 1/16W; RoHS Compliant: Yes; TOLERANCE: +/-1%
R502 R509 R510 = RESISTOR: RES,10.0K OHMS,1.0%,1/16W, 0402; AGILE_LINK: http://sj-agile9app/Agile/PLMServlet?action=OpenEmailObject&classid=10000&objid=146548997; Item Num: P02-11364R; LIFECYCLE_PHASE: Active; Lead Free Status: No; MFR_LIFECYCLE: Active; Manufacturer: Panasonic; Manufacturer Part Num: ERJ-2RKF1002X; Num Pins: 2; PART_SUBCLASS: RESISTORS; POWER: 1/16W; RESISTANCE: 10.0K; RoHS Compliant: Yes; TOLERANCE: +/-1%
R503 R506 = RESISTOR: RES ZERO OHM 1/16W 5% 0402 SMD; Altera Part No.: P02-14020R; Item Num: P02-14020R; Lead Free Status: No; Manufacturer: Panasonic; Manufacturer Part Num: ERJ-2GE0R00X; Num Pins: 2; Part Class: RESISTORS; RoHS Compliant: Yes; Tolerance: 5%
R504 = RES: RES - 200K OHM, 1/16W, 1%, 0402 SMD; Item Num: P02-15992R; Manufacturer: Panasonic; Manufacturer Part Num: ERJ-2RKF2003X; Package: SMD; Part Class: RESISTORS; Type: Resistor
R505 = RESISTOR: RES - 383KOHM, 1/10W, 1%, 0402, SMD; Item Num: P02-17568R; Lead Free Status: No; Manufacturer: Panasonic; Manufacturer Part Num: ERJ-2RKF3833X; Num Pins: 2; Part Class: RESISTORS; Price: 0; RoHS Compliant: Yes; Tolerance: 1%
R507 = RESISTOR: RES - 84.5K OHM, 1/10W, 1%, 0402 SMD; Item Num: P02-17554R; Lead Free Status: No; Manufacturer: Panasonic; Manufacturer Part Num: ERJ-2RKF8452X; Num Pins: 2; Part Class: Resistors; Price: 0; RoHS Compliant: Yes
R511 = RESISTOR: RES - 3.16K OHM, 1/16W, 1%, 0402 SMD; AGILE_LINK: http://sj-agile9app/Agile/PLMServlet?action=OpenEmailObject&classid=10000&objid=146548997; Item Num: P02-15348R; LIFECYCLE_PHASE: Active; Lead Free Status: No; MFR_LIFECYCLE: Active; Manufacturer: Panasonic; Manufacturer Part Num: ERJ-2RKF3161x; Num Pins: 2; PART_SUBCLASS: RESISTORS; POWER: 1/16W; RoHS Compliant: Yes; TOLERANCE: +/-1%
R512 = RESISTOR: Lead Free Status: No; Num Pins: 2; Part Class: RESISTORS; Price: 0; RoHS Compliant: Yes
R513 = RESISTOR: RES, 560 OHM, 5%, 1/16W, 0402, SMD; Item Num: P02-14928R; Lead Free Status: Yes; Manufacturer: Panasonic; Manufacturer Part Num: ERJ-2GEJ561x; Num Pins: 2; Part Class: RESISTORS; Price: 0; RoHS Compliant: Yes
R514 R516 = RESISTOR: RES,100K OHMS,1.0%,1/16W,0402; Item Num: P02-11386R; Lead Free Status: No; Manufacturer: Panasonic; Manufacturer Part Num: ERJ-2RKF1003X; Num Pins: 2; Part Class: Resistors; Price: 0; RoHS Compliant: Yes
R517 R518 R521 = RESISTOR: RES - 2.61K OHM, 1%,1/10W, 0402 SMD; AGILE_LINK: http://sj-agile9app/Agile/PLMServlet?action=OpenEmailObject&classid=10000&objid=146548997; Item Num: P02-16710R; LIFECYCLE_PHASE: Active; Lead Free Status: No; MFR_LIFECYCLE: Active; Manufacturer: Panasonic; Manufacturer Part Num: ERJ-2RKF2611x; Num Pins: 2; PART_SUBCLASS: RESISTORS; POWER: 1/10W; RoHS Compliant: Yes; TOLERANCE: +/-1%
R519 = RESISTOR: RES - 3.57K OHM, 1/16W, 1%, 0402 SMD; Item Num: P02-14569R; Lead Free Status: No; Manufacturer: Vishay; Manufacturer Part Num: CRCW04023K57FKED; Num Pins: 2; Part Class: RESISTORS; Price: 0; RoHS Compliant: Yes; Tolerance: 1%
R520 = RESISTOR: RES,681 OHMS,1.0%,1/16W,0402; AGILE_LINK: http://sj-agile9app/Agile/PLMServlet?action=OpenEmailObject&classid=10000&objid=146548997; Item Num: P02-11396R; LIFECYCLE_PHASE: Active; Lead Free Status: No; MFR_LIFECYCLE: Active; Manufacturer: Panasonic; Manufacturer Part Num: ERJ-2RKF6810X; Num Pins: 2; PART_SUBCLASS: RESISTORS; POWER: 1/16W; RoHS Compliant: Yes; TOLERANCE: +/-1%
U74 = EN6337: REG - 3A VOLTAGE MODE SYNCH BUCK PWM, VIN 2.5-6.6V, DROPOUT V 0.315V, 38-PIN QFN; Item Num: P05-18726R; Manufacturer: Enpirion
U75 = EY1603TI-ADJ: IC - EY1603 40V, LOW QUIESCENT CURRENT, 150MA LINEAR REGULATOR; Item Num: P01-18060R; Manufacturer: Altera
U76 U77 = EY1501DI-ADJ: IC - EY1501DI-ADJ HIGH PERFORMANCE 1A LDO; Item Num: P01-18061R; Manufacturer: Altera
C507 = CAP: CAP CER 6.8PF 25V NP0 0402; AGILE_LINK: http://sj-agile9app/Agile/PLMServlet?action=OpenEmailObject&classid=10000&objid=213459014; Item Num: P03-17804R; Lead Free Status: Lead Free; MFR_LIFECYCLE: Active; Manufacturer: Murata; Manufacturer Part Num: GRM1555C1E6R8CA01D; Num Pins: 2; PART_SUBCLASS: CAPACITORS; RoHS Compliant: Yes
C508 C581 C610-C619 C678 C679 C710 C747 = CAP: CAP - CER, 1uF, 10V, +/-10%, X5R, 0402; Item Num: P03-15479R; Lead Free Status: Yes; Manufacturer: Murata; Manufacturer Part Num: GRM155R61A105KE15D; Num Pins: 2; Part Class: CAPACITORS; RoHS Compliant: Yes
R523 R526 = RESISTOR: RES ZERO OHM 1/16W 5% 0402 SMD; Altera Part No.: P02-14020R; Item Num: P02-14020R; Lead Free Status: No; Manufacturer: Panasonic; Manufacturer Part Num: ERJ-2GE0R00X; Num Pins: 2; Part Class: RESISTORS; Price: 0; RoHS Compliant: Yes; Tolerance: 5%
R524 = RESISTOR: RES ZERO OHM 1/16W 5% 0402 SMD; Item Num: P02-14020R; Lead Free Status: No; Manufacturer: Panasonic; Manufacturer Part Num: ERJ-2GE0R00X; Num Pins: 2; Part Class: RESISTORS; RoHS Compliant: Yes; Tolerance: 5%
R525 = RESISTOR: RES - 348K OHM, 1/10W, 1%, 0402 SMD; Item Num: P02-17553R; Lead Free Status: Yes; Manufacturer: Panasonic; Manufacturer Part Num: ERJ-2RKF3483X; Num Pins: 2; Part Class: RESISTORS; Price: 0; RoHS Compliant: Yes
R527 = RESISTOR: RES,88.7K OHMS,1.0%,1/16W,0402; Item Num: P02-11393R; Manufacturer: Panasonic; Manufacturer Part Num: ERJ-2RKF8872X
R528 = RESISTOR: RES ZERO OHM 1/16W 5% 0402 SMD; Item Num: P02-14020R; Lead Free Status: No; Manufacturer: Panasonic; Manufacturer Part Num: ERJ-2GE0R00X; Num Pins: 2; Part Class: RESISTORS; Price: 0; RoHS Compliant: Yes; Tolerance: 5%
R617 = RESISTOR: RES, 0.003 OHM, 1%, 1/2W, POWERMETAL; AGILE_LINK: http://sj-agile9app/Agile/PLMServlet?action=OpenEmailObject&classid=10000&objid=112752009; Item Num: P02-10702R; LIFECYCLE_PHASE: Active; Lead Free Status: Yes; Manufacturer: Vishay; Manufacturer Part Num: WSL20103L000FEA; Num Pins: 2; PART_SUBCLASS: RESISTORS; POWER: 1/2W; TOLERANCE: +/-1%
U78 = EN5319QI: Regulator, 1.5A sync buck DC-DC converter with integrated inductor; Item Num: P05-18775R; Manufacturer: Enpirion
V63 V64 = SENSE_PAD: Item Num: P23-SENSE; Manufacturer: NONE; Manufacturer Part Num: NONE
C515 C605-C609 = CAP: CAP, CERAMIC, 2.2UF, 10%, 10VDC, X5R, 0603; AGILE_LINK: http://sj-agile9app/Agile/PLMServlet?action=OpenEmailObject&classid=10000&objid=256999866; Item Num: P03-15213R; LIFECYCLE_PHASE: Active; Lead Free Status: Lead Free; MFR_LIFECYCLE: Active; Manufacturer: Murata; Manufacturer Part Num: GRM188R61A225KE34x; Num Pins: 2; PART_SUBCLASS: CAPACITORS; RATED_VOLTAGE: 10V; RoHS Compliant: RoHS Compliant; Supplier Part Num: 490-1545-1-ND; TOLERANCE: +/-10%
C540-C544 = PCAP: CAP - TANT, 330UF, 6.3V, 20%, ESR 0.025-OHM, 2917 LOW PROFILE (1.9MM); AGILE_LINK: http://sj-agile9app/Agile/PLMServlet?action=OpenEmailObject&classid=10000&objid=257237054; Item Num: P03-17661R; LIFECYCLE_PHASE: Active; Lead Free Status: Lead Free; MFR_LIFECYCLE: Active; Manufacturer: Kemet; Manufacturer Part Num: T520V337M006ATE025; Num Pins: 2; PART_SUBCLASS: CAPACITORS; RATED_VOLTAGE: 6.3V; RoHS Compliant: RoHS Compliant; TOLERANCE: +/-20%
C545-C574 = PCAP: CAP CER 220UF 4V 20% X5R 1206; AGILE_LINK: http://sj-agile9app/Agile/PLMServlet?action=OpenEmailObject&classid=10000&objid=257237054; Item Num: P03-17788R; LIFECYCLE_PHASE: Active; Lead Free Status: Lead Free; MFR_LIFECYCLE: Active; Manufacturer: Murata; Manufacturer Part Num: GRM31CR60G227ME11L; Num Pins: 2; PART_SUBCLASS: CAPACITORS; RATED_VOLTAGE: 4V; RoHS Compliant: RoHS Compliant; TOLERANCE: 20%
C575-C579 C585-C604 C670-C676 C751-C753 = PCAP: CAP - TANT, 100UF, 6.3V, 20%, ESR 0.045 OHM, POLY SMD; AGILE_LINK: http://sj-agile9app/Agile/PLMServlet?action=OpenEmailObject&classid=10000&objid=257237054; Item Num: P03-17352R; LIFECYCLE_PHASE: Active; Lead Free Status: Lead Free; MFR_LIFECYCLE: Active; Manufacturer: AVX Corp; Manufacturer Part Num: TCJB107M006R0045; Num Pins: 2; PART_SUBCLASS: CAPACITORS; RATED_VOLTAGE: 6.3V; RoHS Compliant: RoHS Compliant; TOLERANCE: +/-20%
C580 C621-C623 C677 C723 C724 C735 C770 C816 = CAP: CAP - CERAMIC, 4.7UF, 6.3V, 10%, X5R, 0402; AGILE_LINK: http://sj-agile9app/Agile/PLMServlet?action=OpenEmailObject&classid=10000&objid=257560276; Item Num: P03-17432R; LIFECYCLE_PHASE: Active; Lead Free Status: Not Lead Free; MFR_LIFECYCLE: Active; Manufacturer: Murata; Manufacturer Part Num: GRM155R60J475ME87D; Num Pins: 2; PART_SUBCLASS: CAPACITORS; RATED_VOLTAGE: 6.3V; RoHS Compliant: RoHS Compliant; TOLERANCE: +/-10%
C582 C624 C629-C643 C680 C681 C736-C738 C754 C772 = CAP: CAP - CER, .47UF, 10V, X5R, 0402; AGILE_LINK: http://sj-agile9app/Agile/PLMServlet?action=OpenEmailObject&classid=10000&objid=256989651; Item Num: P03-15085R; LIFECYCLE_PHASE: Active; Lead Free Status: Lead Free; MFR_LIFECYCLE: Active; Manufacturer: Murata; Manufacturer Part Num: GRM155R61A474KE15D; Num Pins: 2; PART_SUBCLASS: CAPACITORS; Part Class: CAPACITORS; RATED_VOLTAGE: 10V; RoHS Compliant: RoHS Compliant; Tolerance: +80%/-20%
C583 C584 C625 C644-C663 C682 C683 C730 C755 = CAP: CAP - CERAMIC, 0.22UF, 10V, X5R, 10%, 0402; AGILE_LINK: http://sj-agile9app/Agile/PLMServlet?action=OpenEmailObject&classid=10000&objid=257560276; Item Num: P03-15149R; LIFECYCLE_PHASE: Active; Lead Free Status: Not Lead Free; MFR_LIFECYCLE: Active; Manufacturer: Murata; Manufacturer Part Num: GRM155R61A224KE19D; Num Pins: 2; PART_SUBCLASS: CAPACITORS; RATED_VOLTAGE: 10V; RoHS Compliant: RoHS Compliant; TOLERANCE: +/-10%
C626-C628 C684-C688 C711 C731-C734 C739 C748 C756 C757 C773 C795-C798 = CAP: CAP - CERAMIC,  0.1UF 0402 25VDC Y5V; Dielectric: X5R; Item Num: P03-15057R; LIFECYCLE_PHASE: Active; Lead Free Status: Lead Free; Manufacturer: Murata; Manufacturer Part Num: GRM155F51E104ZA01D; Num Pins: 2; Part Class: CAPACITORS; Price: 0.07; RoHS Compliant: RoHS Compliant; Tolerance: +80%/-20%
C689-C696 C758 C759 C774 = CAP: CAP - CER, 47000PF, 25V, X7R, 0402; Item Num: P03-15073R; Lead Free Status: Yes; Manufacturer: Murata; Manufacturer Part Num: GRM155R71E473KA88D; Num Pins: 2; Part Class: Capacitors; Price: 0; RoHS Compliant: Yes; Supplier Part Num: GRM155R71E473KA88D
C771 = CAP: CAP - CER, 1UF, 10V, +/-10%, X5R, 0402; AGILE_LINK: http://sj-agile9app/Agile/PLMServlet?action=OpenEmailObject&classid=10000&objid=256999866; Item Num: P03-15479R; LIFECYCLE_PHASE: Active; Lead Free Status: Lead Free; MFR_LIFECYCLE: Active; Manufacturer: Murata; Manufacturer Part Num: GRM155R61A105KE15D; Num Pins: 2; PART_SUBCLASS: CAPACITORS; RATED_VOLTAGE: 10V; RoHS Compliant: RoHS Compliant; TOLERANCE: +/-10%
C777-C792 = CAP: CAP - CER 4700PF 50V 10% X7R 0402; AGILE_LINK: http://sj-agile9app/Agile/PLMServlet?action=OpenEmailObject&classid=10000&objid=215384813; Item Num: P03-15074R; LIFECYCLE_PHASE: Active; Lead Free Status: Lead Free; MFR_LIFECYCLE: Active; Manufacturer: Murata; Manufacturer Part Num: GRM155R71H472KA01D; Num Pins: 2; PACKAGING: Tape & Reel (TR); PART_SUBCLASS: CAPACITORS; RATED_VOLTAGE: 50V; RoHS Compliant: RoHS Compliant; Supplier Part Num: GRM155R71H472KA01D; Tolerance: +/-10%
C884-C891 = CAP: CAP - CERAMIC, 4.7UF, 6.3V, 10%, X5R, 0402; AGILE_LINK: http://sj-agile9app/Agile/PLMServlet?action=OpenEmailObject&classid=10000&objid=257560276; CAPACITANCE: 4.7uF; Item Num: P03-17432R; LIFECYCLE_PHASE: Active; Lead Free Status: Not Lead Free; MFR_LIFECYCLE: Active; Manufacturer: Murata; Manufacturer Part Num: GRM155R60J475ME87D; Num Pins: 2; PART_SUBCLASS: CAPACITORS; RATED_VOLTAGE: 6.3V; RoHS Compliant: RoHS Compliant; TOLERANCE: +/-10%
C892-C895 = CAP: CAP - CER 10UF 6.3V 20% X5R 0603; CAPACITANCE: 10uF; Item Num: P03-15733R; Lead Free Status: Lead Free; Manufacturer: Murata; Manufacturer Part Num: GRM188R60J106ME47X; Num Pins: 2; PART_SUBCLASS: CAPACITORS; Part Class: CAPACITORS; RoHS Compliant: RoHS Compliant

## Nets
1.8V: C620.1 C621.1 C622.1 C735.1 C736.1 C737.1 C738.1 C739.1 C740.1 C741.1 C742.1 C743.1 C770.1 C771.1 C772.1 C773.1 C774.1 C775.1 C776.1 C777.2 C778.2 C779.2 C780.2 C781.2 C782.2 C783.2 C784.2 C785.2 C786.2 C787.2 C788.2 C789.2 C790.2 C791.2 C792.2 C793.1 C794.1 ; also on sheet 6 9 15 16 17 19 20 24 27 28 29 30 31 39
1.8V_LOW: R575.1 ; also on sheet 18 39
2.5V: C489.1 C490.1 C491.2 R504.2 R530.1 U74.5(VOUT) U74.6(VOUT) U74.7(VOUT) U74.8(VOUT) U74.9(VOUT) U74.10(VOUT) U74.11(VOUT) ; also on sheet 18 19 21 23 28 29 31 32
2.5V_DAC: R505.1 ; also on sheet 31
2.5V_ENABLE: R502.2 R503.2 U74.27(ENA)
2.5V_FB: C491.1 R504.1 R505.2 R507.2 U74.31(VFB)
2.5V_LLM: R506.2 U74.26(SYNC/LLM)
2.5V_PWRGD: R501.1 U74.28(POK)
2.5V_RLLM: R510.2 U74.29(RLLM)
2.5V_SS: C493.2 U74.30(SS)
3.3V_REG: C488.2 C496.1 C504.1 C508.1 R501.2 R502.1 R513.1 R514.1 R522.2 R523.2 U74.19(PVIN) U74.20(PVIN) U74.21(PVIN) U74.33(AVIN) U76.9(VIN1) U76.10(VIN2) U78.10(TST2) U78.11(TST1) U78.12(TST0) U78.16(AVIN) U78.19(PVIN1) U78.20(PVIN2) ; also on sheet 31 34 41 42
5.0V: C495.1 R508.1 R509.2 R531.1 U75.14(VOUT) ; also on sheet 31 33 36
5V_DAC: R512.1 ; also on sheet 31
12V_G2: C492.1 C494.1 U75.2(VIN) ; also on sheet 31 33 39 40
12V_GROUP3: R532.1 R533.1 R534.1 R547.1 R548.1 R549.1 R562.1 R564.1 R577.1 R578.1 R579.1 ; also on sheet 31 32 33 34
GND: C488.1 C489.2 C490.2 C492.2 C493.1 C494.2 C495.2 C496.2 C497.2 C499.2 C501.2 C502.2 C503.2 C504.2 C505.1 C506.1 C508.2 C515.2 C540.2 C541.2 C542.2 C543.2 C544.2 C545.2 C546.2 C547.2 C548.2 C549.2 C550.2 C551.2 C552.2 C553.2 C554.2 C555.2 C556.2 C557.2 C558.2 C559.2 C560.2 C561.2 C562.2 C563.2 C564.2 C565.2 C566.2 C567.2 C568.2 C569.2 C570.2 C571.2 C572.2 C573.2 C574.2 C575.2 C576.2 C577.2 C578.2 C579.2 C580.2 C581.2 C582.2 C583.2 C584.2 C585.2 C586.2 C587.2 C588.2 C589.2 C590.2 C591.2 C592.2 C593.2 C594.2 C595.2 C596.2 C597.2 C598.2 C599.2 C600.2 C601.2 C602.2 C603.2 C604.2 C605.2 C606.2 C607.2 C608.2 C609.2 C610.2 C611.2 C612.2 C613.2 C614.2 C615.2 C616.2 C617.2 C618.2 C619.2 C620.2 C621.2 C622.2 C623.2 C624.2 C625.2 C626.2 C627.2 C628.2 C629.2 C630.2 C631.2 C632.2 C633.2 C634.2 C635.2 C636.2 C637.2 C638.2 C639.2 C640.2 C641.2 C642.2 C643.2 C644.2 C645.2 C646.2 C647.2 C648.2 C649.2 C650.2 C651.2 C652.2 C653.2 C654.2 C655.2 C656.2 C657.2 C658.2 C659.2 C660.2 C661.2 C662.2 C663.2 C670.2 C671.2 C672.2 C673.2 C674.2 C675.2 C676.2 C677.2 C678.2 C679.2 C680.2 C681.2 C682.2 C683.2 C684.2 C685.2 C686.2 C687.2 C688.2 C689.2 C690.2 C691.2 C692.2 C693.2 C694.2 C695.2 C696.2 C697.2 C698.2 C699.2 C700.2 C701.2 C702.2 C703.2 C704.2 C705.2 C706.2 C707.2 C708.2 C709.1 C710.2 C711.2 C712.2 C713.2 C714.1 C715.1 C716.1 C717.1 C718.1 C719.1 C720.1 C721.1 C722.1 C723.2 C724.2 C725.1 C726.1 C727.1 C728.1 C729.1 C730.2 C731.2 C732.2 C733.2 C734.2 C735.2 C736.2 C737.2 C738.2 C739.2 C740.2 C741.2 C742.2 C743.2 C744.1 C745.1 C746.1 C747.2 C748.2 C749.2 C750.2 C751.2 C752.2 C753.2 C754.2 C755.2 C756.2 C757.2 C758.2 C759.2 C760.2 C761.2 C762.2 C763.2 C764.1 C765.1 C766.1 C767.1 C768.1 C769.1 C770.2 C771.2 C772.2 C773.2 C774.2 C775.2 C776.2 C777.1 C778.1 C779.1 C780.1 C781.1 C782.1 C783.1 C784.1 C785.1 C786.1 C787.1 C788.1 C789.1 C790.1 C791.1 C792.1 C793.2 C794.2 C795.2 C796.2 C797.2 C798.2 C816.2 C884.2 C885.2 C886.2 C887.2 C888.2 C889.2 C890.2 C891.2 C892.2 C893.2 C894.2 C895.2 Q3.1(S1) Q3.2(S2) Q3.3(S3) Q4.1(S1) Q4.2(S2) Q4.3(S3) Q5.1(S1) Q5.2(S2) Q5.3(S3) Q6.2(SOURCE) Q7.2(SOURCE) Q8.2(SOURCE) Q9.1(S1) Q9.2(S2) Q9.3(S3) Q10.1(S1) Q10.2(S2) Q10.3(S3) Q11.1(S1) Q11.2(S2) Q11.3(S3) Q12.2(SOURCE) Q13.2(SOURCE) Q14.2(SOURCE) Q15.1(S1) Q15.2(S2) Q15.3(S3) Q17.1(S1) Q17.2(S2) Q17.3(S3) Q18.2(SOURCE) Q20.2(SOURCE) Q21.1(S1) Q21.2(S2) Q21.3(S3) Q22.1(S1) Q22.2(S2) Q22.3(S3) Q23.1(S1) Q23.2(S2) Q23.3(S3) Q24.2(SOURCE) Q25.2(SOURCE) Q26.2(SOURCE) R506.1 R507.1 R509.1 R510.1 R511.2 R520.2 R521.2 R526.1 R527.1 R538.1 R539.1 R540.1 R553.1 R554.1 R555.1 R568.1 R570.1 R583.1 R584.1 R585.1 U74.13(PGND) U74.14(PGND) U74.15(PGND) U74.16(PGND) U74.17(PGND) U74.18(PGND) U74.32(AGND) U74.39(PGND) U75.8(GND) U75.15(PAD) U76.5(GND) U76.11(EPAD) U77.5(GND) U77.11(EPAD) U78.2(PGND1) U78.3(PGND2) U78.8(PGND3) U78.9(PGND4) U78.15(AGND) U78.25(PGND25) U78.26(PGND26) ; also on sheet 6 7 8 9 10 11 12 13 14 15 16 17 18 19 20 21 23 24 25 27 28 29 30 31 32 33 34 35 36 37 38 39 40 41 42
VCCFUSE_PWRGD: R514.2 U76.4(POK)
VCCIO3V: C795.1 C796.1 C797.1 C798.1 R544.1 R617.2 V64.2(SNS) ; also on sheet 6 15 31
VCCIO3V_ISENSE_N: V64.1(RSNS) ; also on sheet 32
VCCIO3V_ISENSE_P: V63.1(RSNS) ; also on sheet 32
VCCIO3V_LOW: C505.2 C506.2 C507.1 R525.2 R617.1 U78.4(VOUT1) U78.5(VOUT2) U78.6(VOUT3) U78.7(VOUT4) V63.2(SNS)
VCCIO_PWRGD: R522.1 U78.17(POK)
VCCPFUSE_SDM: C497.1 C498.2 C499.1 R515.1 R516.1 R517.1 R529.1 U76.1(VOUT1) U76.2(VOUT2) U77.9(VIN1) U77.10(VIN2) ; also on sheet 15 31
EN_1.8V: R587.2 ; also on sheet 31 39
EN_2.5V: R503.1 R542.2 ; also on sheet 31
EN_5V_3.3V: R543.2 U75.7(EN) ; also on sheet 31 34
EN_S10_VCCIO3V: R524.2 R556.2 ; also on sheet 31
EN_S10_VCCIO_FMCA: R571.2 ; also on sheet 31 33 41
EN_S10_VCCIO_HILO: R557.2 R558.2 ; also on sheet 31 42
EN_S10_VCCPFUSE: R541.2 U76.7(EN) ; also on sheet 31
EN_S10_VCCR: R573.2 ; also on sheet 31 40
EN_S10_VCCRAM: R588.2 ; also on sheet 31 38
EN_S10_VCCT: R586.2 ; also on sheet 31 40
ENET_DVDD: C500.2 C501.1 R518.1 U77.1(VOUT1) U77.2(VOUT2) ; also on sheet 21
ENET_PWRGD: R516.2 U77.4(POK)
FMCA_ADJ: R559.1 ; also on sheet 41
HILO_VDD: R545.1 ; also on sheet 23 42
HILO_VDDQ: R546.1 ; also on sheet 23 42
HILO_VREF: C732.1 C733.1 C734.1 ; also on sheet 15 23
S10_VCC: C540.1 C541.1 C542.1 C543.1 C544.1 C545.1 C546.1 C547.1 C548.1 C549.1 C550.1 C551.1 C552.1 C553.1 C554.1 C555.1 C556.1 C557.1 C558.1 C559.1 C560.1 C561.1 C562.1 C563.1 C564.1 C565.1 C566.1 C567.1 C568.1 C569.1 C570.1 C571.1 C572.1 C573.1 C574.1 C585.1 C586.1 C587.1 C588.1 C589.1 C590.1 C591.1 C592.1 C593.1 C594.1 C595.1 C596.1 C597.1 C598.1 C599.1 C600.1 C601.1 C602.1 C603.1 C604.1 C605.1 C606.1 C607.1 C608.1 C609.1 C610.1 C611.1 C612.1 C613.1 C614.1 C615.1 C616.1 C617.1 C618.1 C619.1 C629.1 C630.1 C631.1 C632.1 C633.1 C634.1 C635.1 C636.1 C637.1 C638.1 C639.1 C640.1 C641.1 C642.1 C643.1 C644.1 C645.1 C646.1 C647.1 C648.1 C649.1 C650.1 C651.1 C652.1 C653.1 C654.1 C655.1 C656.1 C657.1 C658.1 C659.1 C660.1 C661.1 C662.1 C663.1 ; also on sheet 15 16 31 35 36 37
S10_VCCFUSE_DAC: R519.1 ; also on sheet 31
S10_VCCH_GXBL: C709.2 C710.1 C711.1 C712.1 C713.1 ; also on sheet 15 16
S10_VCCH_GXBR: C744.2 C747.1 C748.1 C749.1 C750.1 ; also on sheet 15
S10_VCCIO3V_DAC: R528.1 ; also on sheet 31
S10_VCCIO_FMCA: C623.1 C624.1 C625.1 C626.1 C816.1 ; also on sheet 9 15 25 31 41
S10_VCCIO_HILO: C723.1 C724.1 C730.1 C731.1 ; also on sheet 15 31 42
S10_VCCR_GXB: C670.1 C671.1 C672.1 C673.1 C674.1 C675.1 C676.1 C677.1 C678.1 C679.1 C680.1 C681.1 C682.1 C683.1 C684.1 C685.1 C686.1 C687.1 C688.1 C689.1 C690.1 C691.1 C692.1 C693.1 C694.1 C695.1 C696.1 C697.1 C698.1 C699.1 C700.1 C701.1 C702.1 C703.1 C704.1 C705.1 C706.1 C707.1 C708.1 C714.2 C715.2 C716.2 C717.2 C718.2 C719.2 C720.2 C721.2 C722.2 C725.2 C726.2 C727.2 C728.2 C729.2 C745.2 C746.2 C884.1 C885.1 C886.1 C887.1 C888.1 C889.1 C890.1 C891.1 C892.1 C893.1 C894.1 C895.1 ; also on sheet 15 31 40
S10_VCCR_GXB_LOW: R561.1 ; also on sheet 40
S10_VCCRAM: C575.1 C576.1 C577.1 C578.1 C579.1 C580.1 C581.1 C582.1 C583.1 C584.1 ; also on sheet 15 31 38
S10_VCCRAM_LOW: R576.1 ; also on sheet 38
S10_VCCT_GXB: C515.1 C751.1 C752.1 C753.1 C754.1 C755.1 C756.1 C757.1 C758.1 C759.1 C760.1 C761.1 C762.1 C763.1 C764.2 C765.2 C766.2 C767.2 C768.2 C769.2 ; also on sheet 15 31 40
S10_VCCT_GXB_LOW: R574.1 ; also on sheet 40
VREF_FMCA: C627.1 C628.1 ; also on sheet 15 25
N17943346: C502.1 U76.6(SS)
N17943405: C498.1 R517.2 R519.2 R520.1 U76.3(VFB)
N17943493: C503.1 U77.6(SS)
N17943515: R515.2 U77.7(EN)
N17943561: C500.1 R518.2 R521.1 U77.3(VFB)
N17945238: R508.2 R511.1 R512.2 U75.12(VFB)
N18074853: Q15.4(G) R565.1
N18074855: Q18.3(DRAIN) R562.2 R565.2 R568.2
N18074877: Q18.1(GATE) R571.1
N18075174: Q17.4(G) R567.1
N18075180: Q20.3(DRAIN) R564.2 R567.2 R570.2
N18075192: Q20.1(GATE) R573.1
N18075339: Q3.5(D) R529.2
N18075503: Q5.4(G) R537.1
N18075505: Q8.3(DRAIN) R534.2 R537.2 R540.2
N18075527: Q8.1(GATE) R543.1
N18075594: Q10.4(G) R551.1
N18075596: Q13.3(DRAIN) R548.2 R551.2 R554.2
N18075610: Q13.1(GATE) R557.1
N18075765: Q12.3(DRAIN) R547.2 R550.2 R553.2
N18075771: Q9.4(G) R550.1
N18075779: Q12.1(GATE) R556.1
N18075843: Q3.4(G) R535.1
N18075845: Q6.3(DRAIN) R532.2 R535.2 R538.2
N18075857: Q6.1(GATE) R541.1
N18075915: Q7.3(DRAIN) R533.2 R536.2 R539.2
N18075921: Q4.4(G) R536.1
N18075929: Q7.1(GATE) R542.1
N18082109: Q21.4(G) R580.1
N18082111: Q24.3(DRAIN) R577.2 R580.2 R583.2
N18082123: Q24.1(GATE) R586.1
N18082403: Q22.4(G) R581.1
N18082405: Q25.3(DRAIN) R578.2 R581.2 R584.2
N18082417: Q25.1(GATE) R587.1
N18083281: Q23.4(G) R582.1
N18083283: Q26.3(DRAIN) R579.2 R582.2 R585.2
N18083295: Q26.1(GATE) R588.1
N19038562: R523.1 R524.1 R526.2 U78.18(ENABLE)
N19041179: C507.2 R525.1 R527.2 R528.2 U78.14(VFB)
N19249850: Q4.5(D) R530.2
N19250061: Q5.5(D) R531.2
N19250290: Q9.5(D) R544.2
N19250651: Q10.5(D) R545.2
N19251229: Q15.5(D) R559.2
N19251879: Q17.5(D) R561.2
N19252233: Q21.5(D) R574.2
N19252595: Q22.5(D) R575.2
N19253219: Q23.5(D) R576.2
N20103143: R513.2 U74.22(NC22)
N20151152: Q11.5(D) R546.2
N20151189: Q14.3(DRAIN) R549.2 R552.2 R555.2
N20151195: Q11.4(G) R552.1
N20151203: Q14.1(GATE) R558.1

Not connected (* = marked no-connect by the designer): U74 1(NC(SW)1)* 2(NC(SW)2)* 3(NC3)* 4(NC4)* 12(NC(SW)12)* 23(NC23)* 24(NC24)* 25(NC25)* 34(NC(SW)34)* 35(NC(SW)35)* 36(NC(SW)36)* 37(NC(SW)37)* 38(NC(SW)38)*; U75 1(NC1)* 3(NC2)* 4(NC3)* 5(NC4)* 6(NC5)* 9(NC6)* 10(NC9)* 11(NC8)* 13(NC7)*; U76 8(NC)*; U77 8(NC)*; U78 1(NC(SW)1)* 13(NC)* 21(NC(SW)2)* 22(NC(SW)3)* 23(NC(SW)4)* 24(NC(SW)5)*

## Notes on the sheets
sheet 43
- 50 - Power - LDO 5.0V, 2.5V, 2.4V, 1.0V
- 2.5V
- H = 1.85mm
  Place on bottom side
- 5.0V
- SS -> 22nF * 80kOhm = 1.76msec +/-25%
- VFB=0.75V
  IFB=5nA
- Resistor for LLM mode only.
  Open (DNI) for PWM mode.
- Resistor
  for Min
  Load
- Default to internal pull-up on LLM
  to allow automatic engagement of
  Light Load Mode.
- Min (VIN - VOUT)  =  315mV for PWM
  Min (VIN - VOUT)  =  800mV for LLM
- H = 1.20mm
  Place on bottom side
- connect AGND to
  PGND through a
  single via
- 2.4V
- 1.0V
- H = 1.00mm
  Place on bottom side
- H = 1.00mm
  Place on bottom side
sheet 44
- VCCIO3V
- VCCIO3V Current Sensing
- VCCIO3V
- H = 1.10mm
  Place on bottom side
- connect AGND to
  PGND through a
  single via
sheet 45
- S10 Decoupling
- Place near S10 VCCIO 1.8V
- Place near S10 VCCPT
- Place holder caps
- 0603
- 0402
sheet 46
- Fast Power-Down Discharge
- H = 0.8mm
  Place on bottom side
- H = 0.8mm
  Place on bottom side
- H = 0.8mm
  Place on bottom side
- H = 0.8mm
  Place on bottom side
- H = 0.8mm
  Place on bottom side
- H = 0.8mm
  Place on bottom side
- H = 0.8mm
  Place on bottom side
- H = 0.8mm
  Place on bottom side
- H = 0.8mm
  Place on bottom side
- H = 0.8mm
  Place on bottom side
- H = 0.8mm
  Place on bottom side
